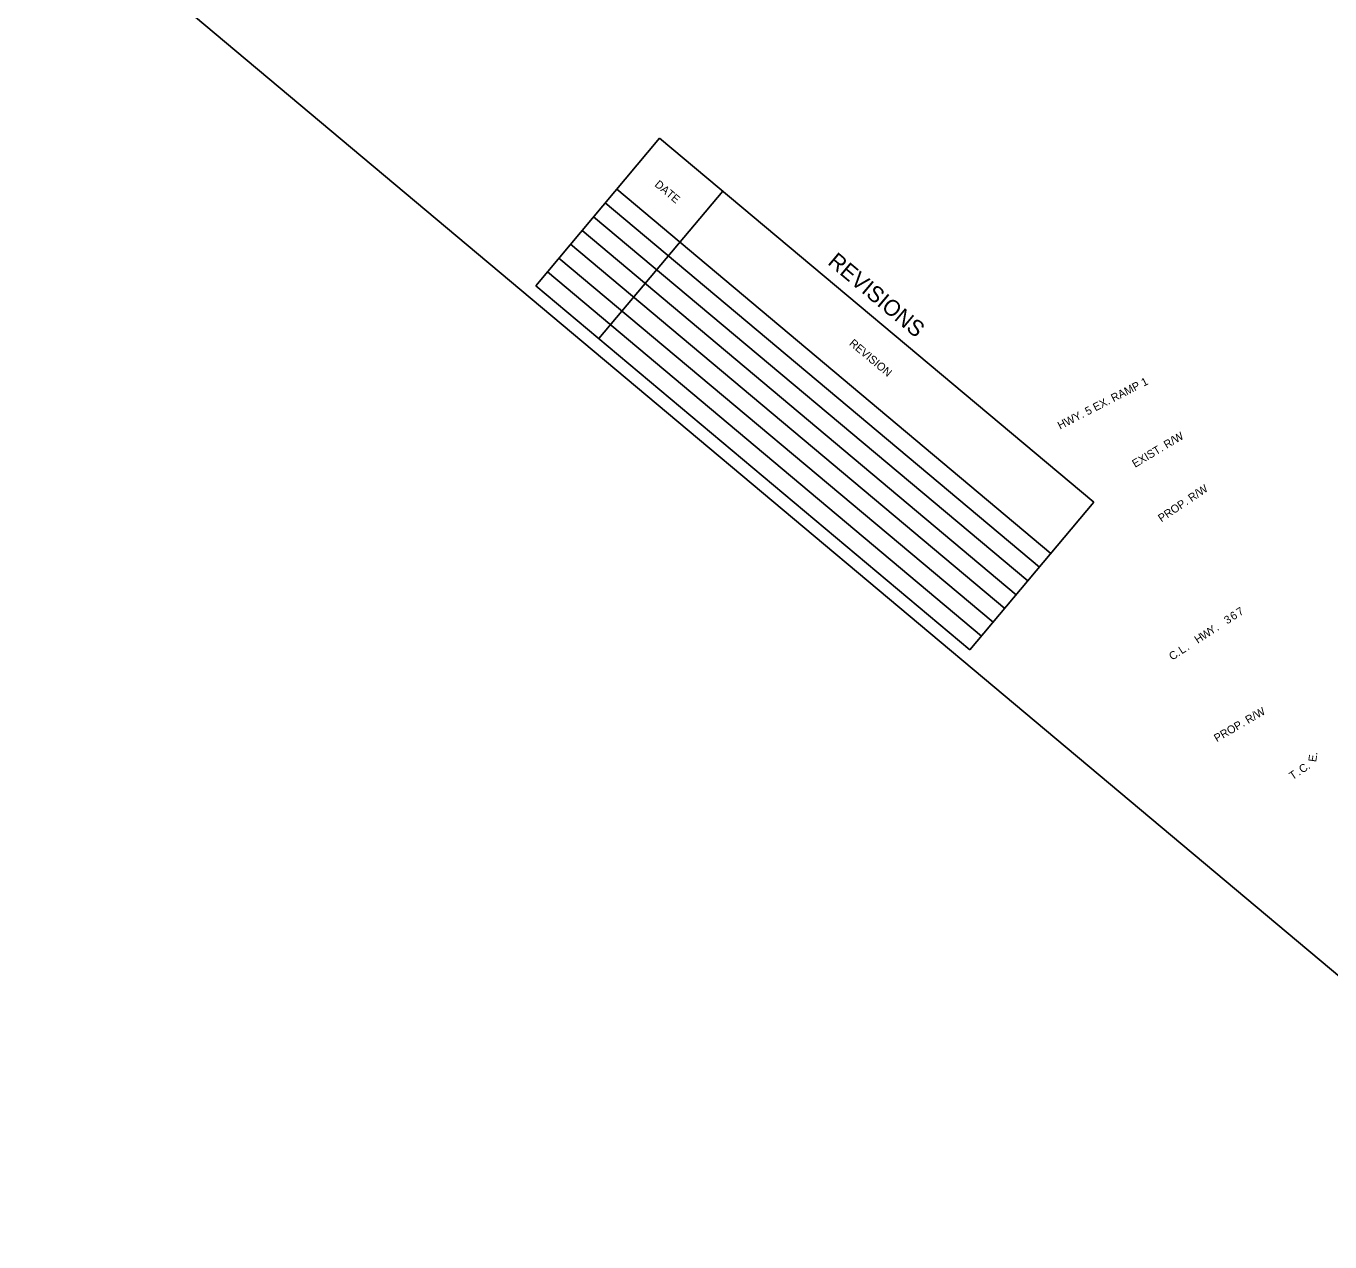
# Model space of a CAD drawing. Extents: x 1292584 to 1294692, y 222754 to 224578.
# Drawn here: x 1292584 to 1293562, y 222754 to 223666 of the extents above; entities that cross this region are included whole.
import ezdxf

# ---------------------------------------------------------------- set-up
doc = ezdxf.new("R2010")
doc.units = 0
for name, color, linetype in [('1', 7, 'Continuous'), ('R_Striping', 7, 'Continuous'), ('S_EDGE_CONCRETE_ANNOT', 7, 'Continuous'), ('S_FIBER_OPTIC_CABLE_ANNOT', 7, 'Continuous')]:
    doc.layers.add(name, color=color, linetype=linetype)

msp = doc.modelspace()

# ---------------------------------------------------------------- linework, layer by layer
at = {"layer": '1'}
msp.add_lwpolyline([(1292584.05, 223779.83), (1293254.04, 224578.3), (1294171.77, 223808.23), (1294139.92, 223770.28), (1294291.79, 223642.84), (1294281.83, 223630.97), (1294336.68, 223584.95), (1294241.87, 223471.95), (1294339.54, 223390), (1293806.17, 222754.35)], close=True, dxfattribs=at)
msp.add_lwpolyline([(1292584.05, 223779.83), (1293254.04, 224578.3), (1294171.77, 223808.23), (1294139.92, 223770.28), (1294291.79, 223642.84), (1294281.83, 223630.97), (1294336.68, 223584.95), (1294241.87, 223471.95), (1294339.54, 223390), (1293806.17, 222754.35)], close=True, dxfattribs=at)
msp.add_lwpolyline([(1292584.05, 223779.83), (1293254.04, 224578.3), (1294171.77, 223808.23), (1294139.92, 223770.28), (1294291.79, 223642.84), (1294281.83, 223630.97), (1294336.68, 223584.95), (1294241.87, 223471.95), (1294339.54, 223390), (1293806.17, 222754.35)], close=True, dxfattribs=at)
msp.add_lwpolyline([(1292584.05, 223779.83), (1293254.04, 224578.3), (1294171.77, 223808.23), (1294139.92, 223770.28), (1294291.79, 223642.84), (1294281.83, 223630.97), (1294336.68, 223584.95), (1294241.87, 223471.95), (1294339.54, 223390), (1293806.17, 222754.35)], close=True, dxfattribs=at)
msp.add_lwpolyline([(1292584.05, 223779.83), (1293254.04, 224578.3), (1294171.77, 223808.23), (1294139.92, 223770.28), (1294291.79, 223642.84), (1294281.83, 223630.97), (1294336.68, 223584.95), (1294241.87, 223471.95), (1294339.54, 223390), (1293806.17, 222754.35)], close=True, dxfattribs=at)
msp.add_lwpolyline([(1292584.05, 223779.83), (1293254.04, 224578.3), (1294171.77, 223808.23), (1294139.92, 223770.28), (1294291.79, 223642.84), (1294281.83, 223630.97), (1294336.68, 223584.95), (1294241.87, 223471.95), (1294339.54, 223390), (1293806.17, 222754.35)], close=True, dxfattribs=at)
at = {"layer": 'S_EDGE_CONCRETE_ANNOT'}
for p, q in [((1293059.11, 223582.29), (1292966.23, 223471.6)), ((1293059.11, 223582.29), (1293384.68, 223309.11)), ((1293106.46, 223542.56), (1293013.58, 223431.87)), ((1293026.97, 223543.99), (1293352.54, 223270.81)), ((1293018.29, 223533.65), (1293343.86, 223260.47)), ((1293009.62, 223523.31), (1293335.19, 223250.13)), ((1293000.94, 223512.97), (1293326.51, 223239.78)), ((1293000.94, 223512.97), (1293326.51, 223239.78)), ((1292992.26, 223502.63), (1293317.83, 223229.44)), ((1292983.58, 223492.28), (1293309.15, 223219.1)), ((1292974.91, 223481.94), (1293300.48, 223208.76)), ((1292966.23, 223471.6), (1293291.8, 223198.42)), ((1293384.68, 223309.11), (1293291.8, 223198.42))]:
    msp.add_line(p, q, dxfattribs=at)

# ---------------------------------------------------------------- texts
at = {"layer": 'R_Striping'}
for s, rotation, p in [('HWY. 5 EX. RAMP 1', 27.24046, (1293359.37, 223363.59)), ('3', 33.12237, (1293484.72, 223217.44)), ('6', 33.06849, (1293489.23, 223220.38)), ('7', 33.01178, (1293493.97, 223223.47)), ('W', 33.33362, (1293467.08, 223205.87)), ('Y', 33.26934, (1293472.44, 223209.4)), ('.', 33.21169, (1293477.26, 223212.55)), ('H', 33.37174, (1293462.58, 223202.91)), ('C', 33.37174, (1293443.45, 223190.3)), ('L', 33.37174, (1293450.63, 223195.03)), ('.', 33.37174, (1293448.18, 223193.42)), ('.', 33.37174, (1293455.13, 223198)), ('E', 81.70679, (1293551.34, 223114.06)), ('.', 81.70679, (1293552.12, 223119.39)), ('T', 34.00129, (1293533.65, 223100.66)), ('C', 34.00129, (1293540.94, 223105.58)), ('.', 34.00129, (1293545.64, 223108.75)), ('.', 34.00129, (1293538.51, 223103.94))]:
    msp.add_text(s, height=6, rotation=rotation, dxfattribs=at).set_placement(p)
at = {"layer": 'S_EDGE_CONCRETE_ANNOT'}
for s, height, p in [('DATE', 6, (1293054.87, 223546.69)), ('REVISIONS', 12, (1293184.46, 223488.21)), ('REVISION', 6, (1293200.76, 223427.54))]:
    msp.add_text(s, height=height, rotation=320.00011, dxfattribs=at).set_placement(p)
at = {"layer": 'S_FIBER_OPTIC_CABLE_ANNOT'}
for s, rotation, p in [('EXIST. R/W', 30.9605, (1293415.59, 223334.93)), ('PROP. R/W', 33.9787, (1293435.36, 223293.98)), ('PROP. R/W', 30.27809, (1293476.92, 223129.05))]:
    msp.add_text(s, height=6, rotation=rotation, dxfattribs=at).set_placement(p)

doc.saveas('drawing.dxf')
